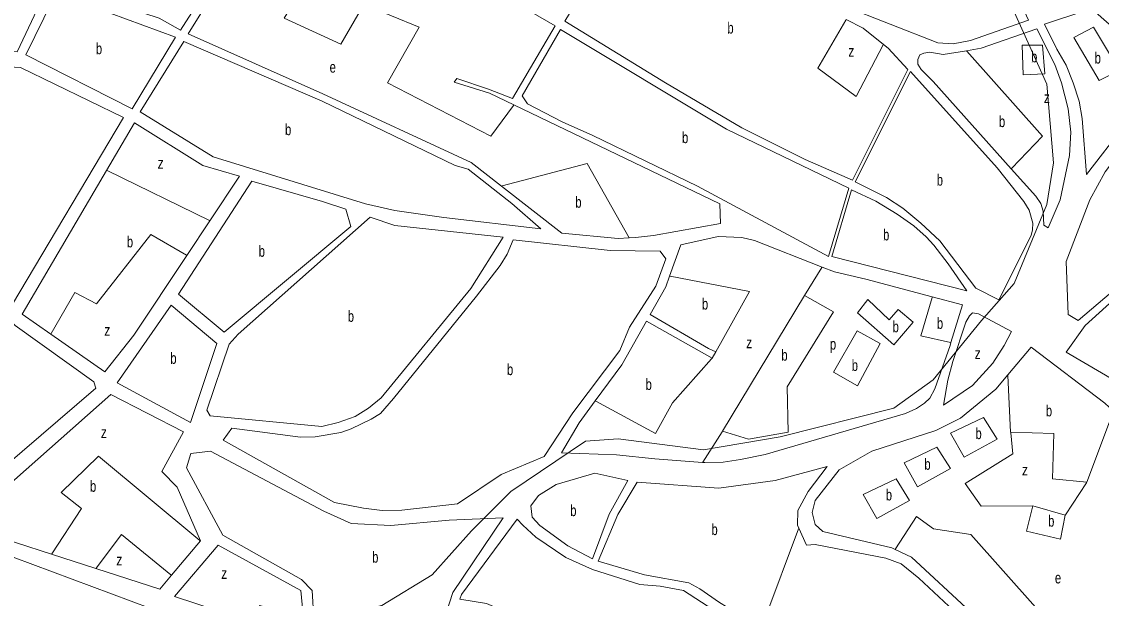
# Model space of a CAD drawing. Extents: x 639657 to 671642, y 222838 to 252123.
# Drawn here: x 644730 to 645696, y 239024 to 239540 of the extents above; entities that cross this region are included whole.
import ezdxf

# ---------------------------------------------------------------- set-up
doc = ezdxf.new("R2010")
doc.units = 0
doc.header["$LTSCALE"] = 4
for name, color, linetype, lineweight in [('1', 7, 'Continuous', 13), ('21', 7, 'Continuous', 13), ('57', 7, 'Continuous', 35)]:
    doc.layers.add(name, color=color, linetype=linetype, lineweight=lineweight)
doc.layers.add('7', color=7, linetype='Continuous')

msp = doc.modelspace()

# ---------------------------------------------------------------- linework, layer by layer
at = {"layer": '1'}
for p, q in [((645351.425, 239244.675), (645344.776, 239247.787)), ((645229.04, 239181.21), (645243.498, 239200.876)), ((645246.03, 239057.6), (645263.75, 239099.26)), ((645432.551, 239071.727), (645425.452, 239087.069))]:
    msp.add_line(p, q, dxfattribs=at)
for points in [[(645375.25, 239802.86), (645292.87, 239667.82), (645372.08, 239615.99), (645403.2, 239592.26), (645414.35, 239582.55), (645427.66, 239574.13), (645464.8, 239554.46), (645550.06, 239520.9), (645563.6, 239520.22), (645579.08, 239522.97), (645631.13, 239541.11), (645608.45, 239590.42), (645589.4, 239624.23), (645579.78, 239650.28), (645531.52, 239698.36), (645480.79, 239696.56), (645469.83, 239698.52), (645459.52, 239704.14)], [(644726.31, 239512.93), (644749.18, 239561.67), (644490.21, 239642.83), (644487.23, 239544.4), (644520.31, 239538.96), (644531.24, 239527.76)], [(644829.12, 239461.99), (644867.92, 239525.95), (644809.31, 239547.57), (644757.99, 239559.71), (644734.04, 239510.12)], [(645645.52, 239537.63), (645656.44, 239515.46), (645664.79, 239501.03), (645671.2, 239485.31), (645676.33, 239468.96), (645679.09, 239453.47), (645682.85, 239403.35), (645716.69, 239446.91), (645734.79, 239472.46), (645736.32, 239479.98), (645735.48, 239489.66), (645733.14, 239501.28), (645723.29, 239520.01), (645690.9, 239548.27), (645682.52, 239549.79)], [(645452.28, 239329.8), (645470.47, 239391.02), (645360.96, 239443.79), (645212.2, 239532.78), (645178.11, 239473.53), (645182.82, 239466.42), (645213.96, 239450.21), (645241.23, 239438.1), (645334.85, 239392.69)], [(644999.07, 239468.72), (644875.22, 239522.28), (644836.2, 239459.18), (644901.43, 239419.07), (645037.75, 239376.96), (645064.17, 239371.08), (645107.8, 239364.94), (645194.62, 239354.59), (645168.66, 239377.45), (645129.82, 239408.09), (645118, 239411.35)], [(644821.37, 239454.27), (644721.99, 239287.27), (644624.86, 239385.49), (644500.26, 239506.98), (644514.02, 239510.6), (644729.07, 239498.96)], [(645604.58, 239291.32), (645633.51, 239348.66), (645634.81, 239353.81), (645634.82, 239359.83), (645631.62, 239371.45), (645626.91, 239378.99), (645602.91, 239409.16), (645525.5, 239495.38), (645476.07, 239396.6), (645503.98, 239382.55), (645518.79, 239373.26), (645534.88, 239359.67), (645551.61, 239343.93), (645583.97, 239301.49)], [(645736.26, 239453.53), (645699.83, 239405.67), (645686.02, 239380.55), (645664.83, 239325.35), (645666.66, 239278.04), (645675.46, 239272.86), (645762.89, 239347.02), (645792.82, 239371.45), (645790.9, 239378.12)], [(644999.31, 239379.1), (644936.19, 239397.28), (644870.68, 239296.19), (644911.43, 239262.14), (645024.61, 239356.75), (645020.11, 239372.28)], [(645575.8, 239299.14), (645559.09, 239323.27), (645546.44, 239340.08), (645539.58, 239347.62), (645528.43, 239357.32), (645513.62, 239367.69), (645494.52, 239379.35), (645472.83, 239389.51), (645455.07, 239329.79)], [(644998.8, 239178), (644898.81, 239187.37), (644895.81, 239192.54), (644915.92, 239251.6), (644923.88, 239260.4), (645041.96, 239365.08), (645064.14, 239357.75), (645161.07, 239347.16), (645132.16, 239301.44), (645051.76, 239203.64), (645040.56, 239194.21), (645028.5, 239186.94), (645013.44, 239181.39)], [(644910.37, 239165.64), (644918.12, 239176.37), (644979.76, 239168.28), (644992.78, 239168.81), (645015.79, 239172.57), (645025.04, 239175.77), (645042.9, 239184.53), (645051.29, 239189.67), (645062.93, 239202.96), (645137.3, 239294.34), (645158.21, 239321.8), (645164.47, 239331.88), (645169.87, 239344.98), (645256.69, 239335.28), (645301.4, 239334.73), (645306.54, 239327.83), (645297.68, 239303.56), (645274.16, 239266.65), (645265.52, 239246.03), (645223.47, 239190.04), (645197.8, 239151.2), (645159.29, 239134.97), (645120.11, 239108.64), (645070.44, 239103.2), (645052.81, 239102.82), (645036.05, 239104.8), (645010.2, 239110.11)], [(644815.73, 239217), (644881.4, 239181.39), (644904.96, 239252.06), (644864, 239286.53)], [(645554.93, 239197.07), (645558.85, 239219.42), (645563.4, 239235.96), (645575.09, 239271.19), (645578.32, 239276.78), (645581.12, 239279.56), (645586.28, 239278.69), (645615.91, 239262.91), (645609.43, 239250.24), (645599.29, 239234.58), (645580.98, 239214.63)], [(645092.53, 238956.34), (645000.96, 238988.35), (644991.67, 239005.75), (644990.22, 239031.34), (644980.57, 239041.03), (644910.19, 239080.73), (644877.66, 239140.99), (644881.56, 239153.66), (644899.18, 239155.99), (645000.43, 239102.34), (645024.91, 239091.31), (645060.59, 239089.28), (645112.62, 239094.29), (645160.99, 239096.31), (645115.91, 239029.58)], [(645255.79, 239099.49), (645240.87, 239059.55), (645218.97, 239071.22), (645193.86, 239089.34), (645187, 239096.89), (645185.73, 239106.99), (645192.63, 239116.22), (645208.56, 239126.06), (645243.19, 239136.08), (645272.63, 239129.55)], [(644687.17, 239074.11), (644845.82, 239015.3), (644763.56, 238923.04), (644737.11, 238912.35), (644708.35, 238925.95), (644584.28, 239083.15), (644667.04, 239104.03), (644675.59, 239082.95)], [(645178.6, 239089.82), (645173.46, 239094.99), (645123.65, 239027.84), (645122.35, 239023.54), (645145.99, 239019.82), (645175.62, 239007.28), (645172.81, 239001.26), (645143.18, 239012.95), (645120.83, 239017.1), (645101.77, 238953.52), (645267.79, 238896.32), (645354.47, 239010.44), (645322.49, 239031.38), (645301.65, 239035.31), (645283.38, 239036.65), (645240.85, 239050.09), (645217.23, 239060.9), (645190.19, 239079.03)], [(644866.9, 239026.01), (644984.11, 238987.5), (644980.12, 239031.36), (644905.88, 239071.93)]]:
    msp.add_lwpolyline(points, close=True, dxfattribs=at)
for points in [[(645170.51, 239465.577), (645148.88, 239475.98), (645117.3, 239485.74), (645119.68, 239488.96), (645148.03, 239479.64), (645169.29, 239471.19), (645207.48, 239536.24), (645040.66, 239632.81), (644996.65, 239555.2)], [(645266.545, 239623.247), (645216.3, 239540.3), (645306.24, 239485.22), (645374.51, 239445.04), (645431.19, 239416.72), (645473.71, 239398.33)], [(644880.62, 239610.743), (644912.1, 239594.2), (644872.44, 239532.17), (644853.34, 239543.17), (644798.38, 239561.35), (644760.8, 239568.09)], [(644977.732, 239563.767), (644917.68, 239590.96), (644879.31, 239529.15), (644999.7, 239475.53), (645132.41, 239414.1), (645159.678, 239392.846)], [(645501.388, 239519.597), (645483.24, 239533.98), (645468.015, 239541.757)], [(645638.42, 239533.57), (645588.74, 239516.07), (645575.514, 239513.929)], [(645615.725, 239408.445), (645637.67, 239383.91), (645642.17, 239377.45), (645644.09, 239370.56), (645644.92, 239357.87), (645648.78, 239355.71), (645659.37, 239380.62), (645667.84, 239420.17), (645668.96, 239441.02), (645666.64, 239462.1), (645660.67, 239485.13), (645654.69, 239501.48), (645638.42, 239533.57)], [(645473.71, 239398.33), (645523.14, 239497.1), (645505.56, 239516.29), (645501.388, 239519.597)], [(644796.6, 239212.31), (644794.68, 239217.9), (644724.31, 239268.13), (644486.72, 239506.79), (644459.87, 239511.58), (644386.177, 239514.293)], [(645575.514, 239513.929), (645554.77, 239510.57), (645542.74, 239512.53), (645537.58, 239511.69), (645533.92, 239510.19), (645531.98, 239506.11), (645531.97, 239501.81), (645535.18, 239497.29), (645545.9, 239486.51), (645615.725, 239408.445)], [(645273.718, 239346.528), (645279.5, 239346.83), (645295.41, 239348.72), (645355.62, 239359.3), (645354.8, 239376.94), (645170.51, 239465.577)], [(644806.092, 239406.962), (644831.03, 239449.52), (644892.18, 239411.35), (644925.25, 239401.82)], [(644756.322, 239260.529), (644730.78, 239278.44), (644806.092, 239406.962)], [(644925.25, 239401.82), (644898.64, 239361.796), (644878.109, 239330.917)], [(645159.678, 239392.846), (645213.52, 239350.88), (645263.81, 239346.01), (645273.718, 239346.528)], [(645814.49, 239356.13), (645800.13, 239372.94), (645766.11, 239344.65), (645681.9, 239268.32), (645664.65, 239244.5), (645724.53, 239209.51), (645713.77, 239200.73), (645856.314, 239047.534)], [(645309.96, 239312.406), (645319.9, 239340.27), (645353.45, 239347.7), (645374.72, 239346.99), (645385.89, 239344.17), (645446.407, 239320.537)], [(644878.109, 239330.917), (644830.64, 239259.52), (644804.58, 239226.69), (644756.322, 239260.529)], [(645446.407, 239320.537), (645457.41, 239316.24), (645485.55, 239309.71), (645544.969, 239293.863)], [(645344.776, 239247.787), (645292.46, 239278.21), (645306.49, 239302.68), (645309.96, 239312.406)], [(645544.969, 239293.863), (645571.9, 239286.68), (645561.663, 239253.051)], [(645243.498, 239200.876), (645267.21, 239233.13), (645289.22, 239272.2), (645347.969, 239239.001), (645351.425, 239244.675)], [(645561.663, 239253.051), (645560.85, 239250.38), (645547.22, 239211.5), (645542.91, 239203.13), (645537.95, 239198.84), (645530.85, 239193.91), (645521.17, 239189.64), (645395.56, 239152.8), (645373.41, 239148.34), (645357.93, 239146.02), (645341.38, 239145.64), (645339.507, 239145.74), (645296.77, 239149.05)], [(645612.68, 239224.176), (645633.56, 239248.78), (645699.43, 239198.94), (645707.226, 239191.503)], [(645548.07, 239174.39), (645570.23, 239185.3), (645601.88, 239211.45), (645612.68, 239224.176)], [(644634.967, 239110.493), (644698.89, 239128.04), (644713.752, 239140.858), (644796.6, 239212.31)], [(644756.902, 239063.685), (644693.85, 239083.99), (644689.59, 239100.12), (644810.13, 239206.69)], [(644810.13, 239206.69), (644874.94, 239173.23), (644855.53, 239137.81), (644869.25, 239123.81), (644890.2, 239075.61), (644864.282, 239044.9)], [(645296.77, 239149.05), (645262.51, 239152.74), (645213.321, 239154.379), (645229.04, 239181.21)], [(645461.58, 239139.15), (645490.85, 239155.84), (645548.07, 239174.39)], [(645425.452, 239087.069), (645424.29, 239089.58), (645424.75, 239102.7), (645434.03, 239119.87), (645450.84, 239142.19), (645404.39, 239129.62), (645353.86, 239122.88)], [(645447.06, 239084.15), (645440.2, 239090.19), (645437.43, 239101.16), (645440.24, 239111.9), (645461.58, 239139.15)], [(645353.86, 239122.88), (645280.79, 239128.23), (645263.75, 239099.26)], [(645511.869, 239068.072), (645508.72, 239069.58), (645447.06, 239084.15)], [(645432.551, 239071.727), (645440.16, 239072.56), (645503.54, 239060.14), (645517.06, 239055.15), (645532.94, 239042.43), (645559.75, 239017.42), (645592.97, 238974.98), (645684.22, 238844.25), (645692.14, 238829.82), (645694.9, 238816.27), (645688.58, 238779.53), (645688.74, 238757.39), (645692.003, 238729.72), (645693.315, 238718.59)], [(644864.282, 239044.9), (644853.8, 239032.48), (644796.583, 239050.906), (644756.902, 239063.685)], [(645704.18, 238829.79), (645699.9, 238840.55), (645579.3, 239012.21), (645526.32, 239061.15), (645511.869, 239068.072)], [(645395.002, 239005.463), (645387.77, 239006.05), (645368.44, 239012.34), (645354.49, 239020.55), (645336.89, 239032.85), (645327.23, 239038.25), (645287.47, 239045.44), (645246.03, 239057.6)]]:
    msp.add_lwpolyline(points, dxfattribs=at)
at = {"layer": '21'}
for p, q in [((645625.287, 239518.75), (645643.568, 239518.75)), ((645430.677, 239294.934), (645357.157, 239173.786))]:
    msp.add_line(p, q, dxfattribs=at)
for points in [[(644977.732, 239563.767), (644977.427, 239563.267), (644965.13, 239543.137), (645015.911, 239519.766), (645036.224, 239555.33), (645085.99, 239535.008), (645057.552, 239485.219), (645149.974, 239437.462), (645170.145, 239465.077), (645170.51, 239465.577)], [(645501.388, 239519.597), (645501.126, 239519.097), (645477.005, 239473.025), (645442.474, 239498.428), (645467.72, 239541.257), (645468.015, 239541.757)], [(645625.287, 239518.75), (645626.303, 239492.331), (645645.6, 239493.347), (645643.568, 239518.75)], [(645575.514, 239513.929), (645575.959, 239513.429), (645643.568, 239437.461), (645616.205, 239408.945), (645615.725, 239408.445)], [(645159.678, 239392.846), (645160.178, 239392.978), (645236.302, 239413.076), (645273.64, 239346.667), (645273.718, 239346.528)], [(644806.092, 239406.962), (644806.592, 239406.718), (644898.14, 239362.04), (644898.64, 239361.796)], [(644756.322, 239260.529), (644756.61, 239261.029), (644777.743, 239297.75), (644797.04, 239287.589), (644845.79, 239349.572), (644877.609, 239331.206), (644878.109, 239330.917)], [(645430.677, 239294.934), (645446.1, 239320.037), (645446.407, 239320.537)], [(645351.425, 239244.675), (645381.532, 239298.767), (645310.46, 239312.311), (645309.96, 239312.406)], [(645357.157, 239173.786), (645380.517, 239166.674), (645416.064, 239172.77), (645415.048, 239213.414), (645456.689, 239280.477), (645430.677, 239294.934)], [(645544.969, 239293.863), (645544.824, 239293.363), (645534.892, 239259.139), (645561.163, 239253.165), (645561.663, 239253.051)], [(645347.969, 239239.001), (645347.523, 239238.501), (645312.47, 239199.189), (645297.235, 239171.754), (645243.998, 239200.605), (645243.498, 239200.876)], [(645612.68, 239224.176), (645612.704, 239223.676), (645615.126, 239172.77)], [(645615.126, 239172.77), (645653.72, 239171.754), (645652.705, 239131.11), (645683.173, 239128.062), (645707.226, 239191.503)], [(645357.157, 239173.786), (645356.842, 239173.286), (645339.731, 239146.095), (645339.507, 239145.74)], [(645615.126, 239172.77), (645615.179, 239172.27), (645617.158, 239153.464), (645574.501, 239127.046), (645588.72, 239106.724), (645634.965, 239106.858)], [(644890.2, 239075.61), (644889.7, 239076.026), (644799.071, 239151.432), (644765.555, 239118.917), (644783.837, 239104.691), (644757.23, 239064.185), (644756.902, 239063.685)], [(645683.173, 239128.062), (645682.846, 239127.562), (645664.204, 239099.095), (645663.877, 239098.595)], [(645704.18, 238829.79), (645704.68, 238830.166), (645727.861, 238847.618), (645710.595, 238914.681), (645637.47, 239016.291), (645579.58, 239081.321), (645546.064, 239086.402), (645530.829, 239097.579), (645512.19, 239068.572), (645511.869, 239068.072)], [(644796.583, 239050.906), (644796.958, 239051.406), (644819.383, 239081.321), (644863.782, 239045.306), (644864.282, 239044.9)], [(645425.452, 239087.069), (645425.265, 239086.568), (645395.189, 239005.963), (645395.002, 239005.463)]]:
    msp.add_lwpolyline(points, dxfattribs=at)
for points in [[(645671.708, 239525.759), (645689.271, 239535.007), (645712.631, 239496.395), (645694.35, 239487.25)], [(645487.209, 239291.416), (645478.017, 239279.461), (645510.517, 239251.01), (645527.783, 239271.332), (645514.579, 239282.509), (645506.454, 239273.364)], [(645477.918, 239263.513), (645456.689, 239226.624), (645478.017, 239214.43), (645498.329, 239252.026)], [(645561.432, 239171.857), (645590.752, 239185.98), (645602.94, 239166.674), (645573.487, 239150.417)], [(645519.791, 239145.438), (645549.111, 239159.561), (645561.299, 239140.255), (645531.846, 239123.998)], [(645483.228, 239116.987), (645512.548, 239131.11), (645524.736, 239111.804), (645495.283, 239095.547)], [(645634.965, 239106.858), (645629.345, 239084.369), (645659.814, 239077.257), (645663.877, 239098.595)]]:
    msp.add_lwpolyline(points, close=True, dxfattribs=at)
at = {"layer": '57', "lineweight": 13}
msp.add_lwpolyline([(645618.268, 239548.771), (645647.634, 239484.134), (645653.507, 239413.621), (645647.634, 239376.406), (645618.268, 239305.893), (645588.903, 239272.595), (645545.833, 239219.711), (645510.594, 239194.248), (645408.793, 239168.785), (645340.274, 239157.032), (645263.923, 239166.826), (645234.557, 239164.867), (645167.995, 239119.817), (645132.756, 239084.561), (645097.518, 239045.387), (645052.49, 239017.965), (644997.675, 239006.213), (644942.859, 239017.965)], dxfattribs=at)

# ---------------------------------------------------------------- texts
at = {"layer": '7'}
for s, width, p in [('b', 0.75, (645361.682, 239529.315)), ('b', 0.75, (644796.576, 239510.85)), ('z', 0.8, (645469.896, 239508.589)), ('b', 0.75, (645633.412, 239503.508)), ('b', 0.75, (645690.288, 239502.492)), ('e', 0.75, (645005.754, 239494.364)), ('z', 0.8, (645644.821, 239467.125)), ('b', 0.75, (644965.894, 239438.435)), ('b', 0.75, (645604.628, 239445.656)), ('b', 0.75, (645321.085, 239431.29)), ('z', 0.8, (644851.884, 239408.505)), ('b', 0.75, (645549.006, 239393.35)), ('b', 0.75, (645225.59, 239373.575)), ('b', 0.75, (645500.985, 239344.325)), ('b', 0.75, (644824.315, 239338.105)), ('b', 0.75, (644942.332, 239329.71)), ('b', 0.75, (645338.876, 239282.509)), ('b', 0.75, (645022.013, 239271.54)), ('b', 0.75, (645549.111, 239265.235)), ('z', 0.8, (644804.149, 239259.139)), ('b', 0.75, (645509.501, 239262.187)), ('z', 0.8, (645378.485, 239247.962)), ('b', 0.75, (645409.97, 239236.785)), ('p', 0.75, (645453.356, 239246.67)), ('z', 0.8, (645582.945, 239238.315)), ('b', 0.75, (644863.215, 239233.96)), ('b', 0.75, (645472.939, 239227.64)), ('b', 0.75, (645164.436, 239223.9)), ('b', 0.75, (645288.46, 239210.625)), ('b', 0.75, (645646.611, 239186.996)), ('z', 0.8, (644801.102, 239167.69)), ('b', 0.75, (645583.642, 239166.674)), ('b', 0.75, (645537.939, 239139.239)), ('z', 0.8, (645625.283, 239134.158)), ('b', 0.75, (644791.347, 239119.585)), ('b', 0.75, (645503.408, 239111.804)), ('b', 0.75, (645221.024, 239097.815)), ('b', 0.75, (645347.406, 239080.866)), ('b', 0.75, (645648.642, 239088.434)), ('z', 0.8, (644814.915, 239053.735)), ('b', 0.75, (645043.804, 239056.165)), ('z', 0.8, (644908.759, 239041.693)), ('e', 0.75, (645654.736, 239037.629))]:
    msp.add_text(s, height=10, dxfattribs=dict(at, width=width)).set_placement(p)

doc.saveas('drawing.dxf')
